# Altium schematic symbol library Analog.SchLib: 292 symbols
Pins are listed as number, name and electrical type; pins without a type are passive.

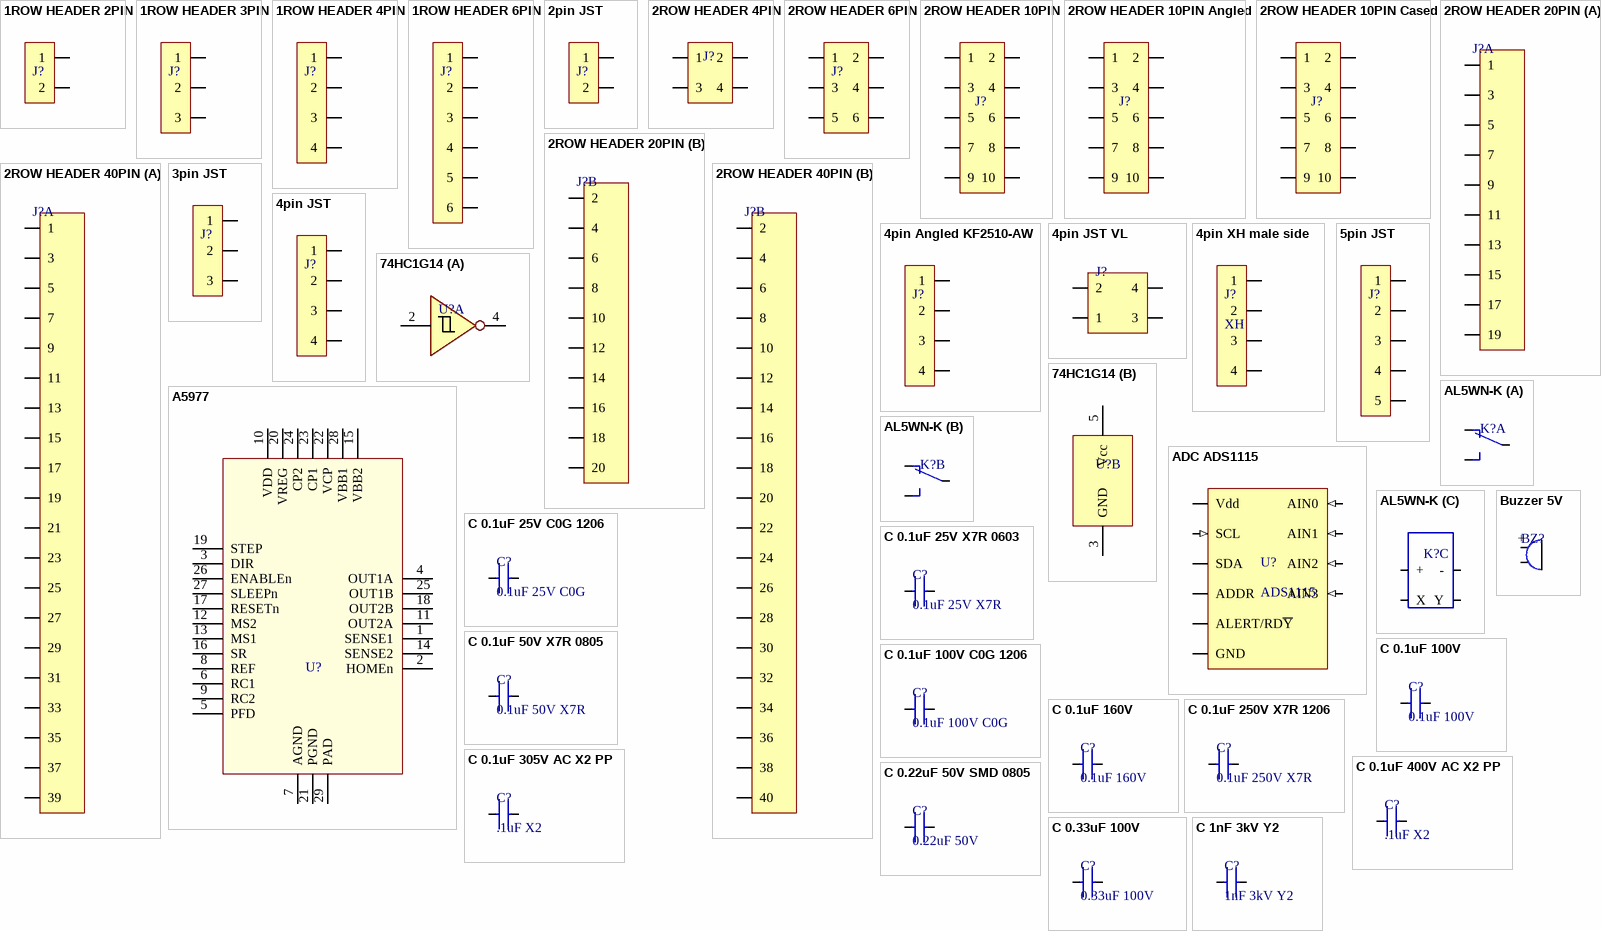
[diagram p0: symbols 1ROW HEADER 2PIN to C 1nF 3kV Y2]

## 1ROW HEADER 2PIN
designator J?  (value not drawn)
footprint 1ROW HEADER 2PIN (PEC02SAAN)
pins: 1, 2

## 1ROW HEADER 3PIN
designator J?  (value not drawn)
footprint 1ROW HEADER 3PIN (PEC03SAAN)
pins: 1, 2, 3

## 1ROW HEADER 4PIN
designator J?  (value not drawn)
footprint 1ROW HEADER 4PIN (PEC04SAAN)
pins: 1, 2, 3, 4

## 1ROW HEADER 6PIN
designator J?  (value not drawn)
footprint 1ROW HEADER 6PIN (PEC06SAAN)
pins: 1, 2, 3, 4, 5, 6

## 2pin JST
designator J?  (value not drawn)
footprint 2pin JST XH 2.5mm (B2B-XH)
pins: 1, 2

## 2ROW HEADER 4PIN
designator J?  (value not drawn)
footprint 2ROW HEADER 4PIN (PEC02SAAN)
pins: 1, 2, 3, 4

## 2ROW HEADER 6PIN
designator J?  (value not drawn)
footprint 2ROW HEADER 6PIN
pins: 1, 2, 3, 4, 5, 6

## 2ROW HEADER 10PIN
designator J?  (value not drawn)
footprint 2ROW HEADER 10PIN (PEC02SAAN)
pins: 1, 2, 3, 4, 5, 6, 7, 8, 9, 10

## 2ROW HEADER 10PIN Angled
designator J?  (value not drawn)
footprint 2ROW HEADER 10PIN Angled (2X05P)
pins: 1, 2, 3, 4, 5, 6, 7, 8, 9, 10

## 2ROW HEADER 10PIN Cased
designator J?  (value not drawn)
footprint 2ROW HEADER 10PIN CASED (PEC02SAAN)
pins: 1, 2, 3, 4, 5, 6, 7, 8, 9, 10

## 2ROW HEADER 20PIN
designator J?  (value not drawn)
footprint 2ROW HEADER 20PIN
part A pins: 1, 3, 5, 7, 9, 11, 13, 15, 17, 19
part B pins: 2, 4, 6, 8, 10, 12, 14, 16, 18, 20

## 2ROW HEADER 40PIN
designator J?  (value not drawn)
footprint 2ROW HEADER 40PIN
part A pins: 1, 3, 5, 7, 9, 11, 13, 15, 17, 19, 21, 23, 25, 27, 29, 31, 33, 35, 37, 39
part B pins: 2, 4, 6, 8, 10, 12, 14, 16, 18, 20, 22, 24, 26, 28, 30, 32, 34, 36, 38, 40

## 3pin JST
designator J?  (value not drawn)
footprint 3pin JST XH 2.5mm (B3B-XH)
pins: 1, 2, 3

## 4pin Angled KF2510-AW
designator J?  (value not drawn)
footprint 4pin KF2510-AW (KF2510-AW)
pins: 1, 2, 3, 4

## 4pin JST
designator J?  (value not drawn)
footprint 4pin JST XH 2.5mm (B4B-XH)
pins: 1, 2, 3, 4

## 4pin JST VL
designator J?  (value not drawn)
footprint 4pin JST VL (B04P-VL)
pins: 1, 2, 3, 4

## 4pin XH male side
designator J?, comment XH
footprint 4pin XH male side (S4B-XH-A-1)
pins: 1, 2, 3, 4

## 5pin JST
designator J?  (value not drawn)
footprint 5pin JST XH 2.5mm (B4B-XH)
pins: 1, 2, 3, 4, 5

## 74HC1G14
designator U?  (value not drawn)
footprint SOT-23-5-TI
part A pins: 2 In, 4 Out
part B pins: 3 GND, 5 Vcc

## A5977
designator U?  (value not drawn)
footprint TSSOP-28-EP
pins: 1 SENSE1, 2 HOMEn, 3 DIR, 4 OUT1A, 5 PFD, 6 RC1, 7 AGND, 8 REF, 9 RC2, 10 VDD, 11 OUT2A, 12 MS2, 13 MS1, 14 SENSE2, 15 VBB2, 16 SR, 17 RESETn, 18 OUT2B, 19 STEP, 20 VREG, 21 PGND, 22 VCP, 23 CP1, 24 CP2, 25 OUT1B, 26 ENABLEn, 27 SLEEPn, 28 VBB1, 29 PAD

## ADC ADS1115
designator U?, comment ADS1115
footprint MSOP-10-MCP; pin to pad ADDR>1 AIN0>4 AIN1>5 AIN2>6 AIN3>7 ALERT/RDY\>2 GND>3 SCL>10 SDA>9 Vdd>8
pins: ADDR, AIN0 (in), AIN1 (in), AIN2 (in), AIN3 (in), ALERT/RDY\, GND, SCL (in), SDA (io), Vdd (power)

## AL5WN-K
designator K?  (value not drawn)
Takamisawa Relay AL5WN-K
footprint Relay DIP10; pin to pad +>1 ->10 KA>3 KB>8 NCA>2 NCB>9 NOA>4 NOB>7 X>5 Y>6
footprint Relay DIP10; pin to pad +>1 ->10 KA>3 KB>8 NCA>2 NCB>9 NOA>4 NOB>7 X>5 Y>6
part A pins: KA, NCA, NOA
part B pins: KB, NCB, NOB
part C pins: +, -, X, Y

## Buzzer 5V
designator BZ?, comment BUZZER, 12mm X 9.5mm  (value not drawn)
footprint Buzzer (PEC02SAAN)
pins: +, -

## C 0.1uF 25V C0G 1206
designator C?, comment 0.1uF 25V C0G
footprint C np SMD 1206
pins: 1, 2

## C 0.1uF 25V X7R 0603
designator C?, comment 0.1uF 25V X7R
footprint C np SMD 0603
pins: 1, 2

## C 0.1uF 50V X7R 0805
designator C?, comment 0.1uF 50V X7R
footprint C np SMD 0805
pins: 1, 2

## C 0.1uF 100V
designator C?, comment 0.1uF 100V
footprint C np rect L5 D5 W7.2
pins: 1, 2

## C 0.1uF 100V C0G 1206
designator C?, comment 0.1uF 100V C0G
footprint C np SMD 1206
pins: 1, 2

## C 0.1uF 160V
designator C?, comment 0.1uF 160V
footprint C np rect L5 D9 W7.2
pins: 1, 2

## C 0.1uF 250V X7R 1206
designator C?, comment 0.1uF 250V X7R
footprint C np SMD 1206
pins: 1, 2

## C 0.1uF 305V AC X2 PP
designator C?, comment .1uF X2
footprint C np rect L15 D5.5 W18 (PP 0.1uF 630V)
pins: 1, 2

## C 0.1uF 400V AC X2 PP
designator C?, comment .1uF X2
footprint C np rect L15 D9 W18 (MKP1J031004J)
pins: 1, 2

## C 0.22uF 50V SMD 0805
designator C?, comment 0.22uF 50V
footprint C np SMD 0805
pins: 1, 2

## C 0.33uF 100V
designator C?, comment 0.33uF 100V
footprint C np rect L15 D8 W18 (PP 0.33uF 100V)
pins: 1, 2

## C 1nF 3kV Y2
designator C?, comment 1nF 3kV Y2
footprint C np Ceramic L7.5
pins: 1, 2

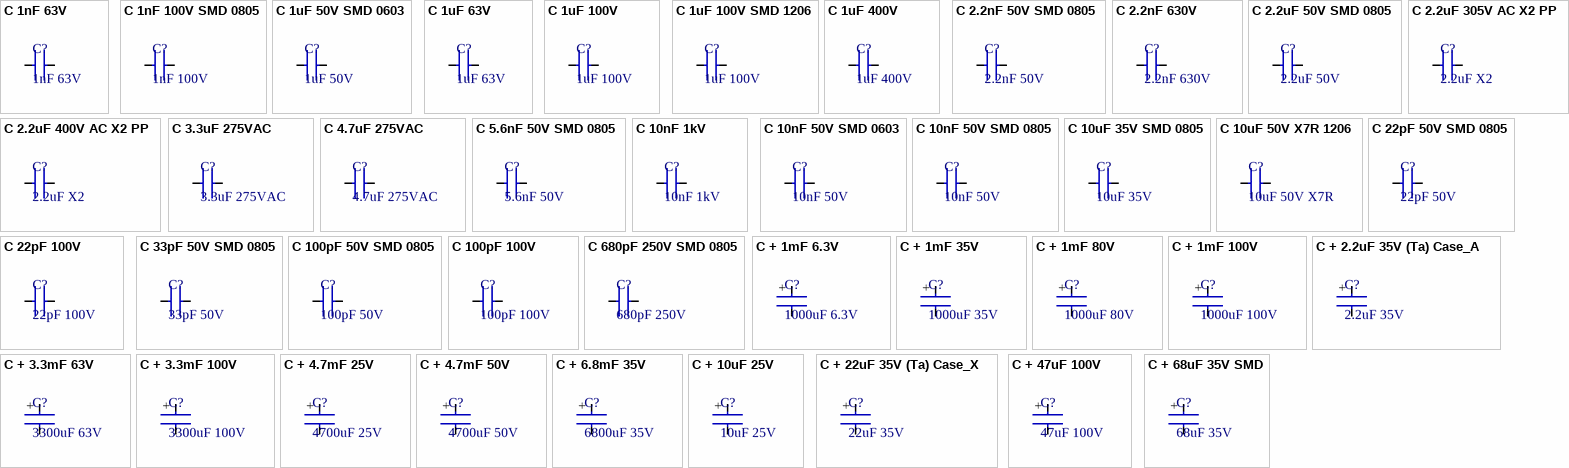
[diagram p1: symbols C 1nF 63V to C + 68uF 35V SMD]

## C 1nF 63V
designator C?, comment 1nF 63V
footprint C np rect L5 D2.5 W7.2
pins: 1, 2

## C 1nF 100V SMD 0805
designator C?, comment 1nF 100V
footprint C np SMD 0805
pins: 1, 2

## C 1uF 50V SMD 0603
designator C?, comment 1uF 50V
footprint C np SMD 0603
pins: 1, 2

## C 1uF 63V
designator C?, comment 1uF 63V
footprint C np rect L5 D6 W7.2
pins: 1, 2

## C 1uF 100V
designator C?, comment 1uF 100V
footprint C np rect L5 D7.2 W7.2
pins: 1, 2

## C 1uF 100V SMD 1206
designator C?, comment 1uF 100V
footprint C np SMD 1206
pins: 1, 2

## C 1uF 400V
designator C?, comment 1uF 400V
footprint C np rect L27.5 D11 W31 (MKP4-1/400/5P27)
pins: 1, 2

## C 2.2nF 50V SMD 0805
designator C?, comment 2.2nF 50V
footprint C np SMD 0805
pins: 1, 2

## C 2.2nF 630V
designator C?, comment 2.2nF 630V
footprint C np rect L5 D3 W7.2
pins: 1, 2

## C 2.2uF 50V SMD 0805
designator C?, comment 2.2uF 50V
footprint C np SMD 0805
pins: 1, 2

## C 2.2uF 305V AC X2 PP
designator C?, comment 2.2uF X2
footprint C np rect L27.5 D14 W31.5 (B32924C3225M189)
pins: 1, 2

## C 2.2uF 400V AC X2 PP
designator C?, comment 2.2uF X2
footprint C np rect L37.5 D20 W41.5 (MKP1J042207G)
pins: 1, 2

## C 3.3uF 275VAC
designator C?, comment 3.3uF 275VAC
footprint C np rect L27.5 D22 W31.5 (MP2335KGF8RLC)
pins: 1, 2

## C 4.7uF 275VAC
designator C?, comment 4.7uF 275VAC
footprint C np rect L27.5 D22 W31.5 (MP2335KGF8RLC)
pins: 1, 2

## C 5.6nF 50V SMD 0805
designator C?, comment 5.6nF 50V
footprint C np SMD 0805
pins: 1, 2

## C 10nF 1kV
designator C?, comment 10nF 1kV
footprint C np Ceramic L5
pins: 1, 2

## C 10nF 50V SMD 0603
designator C?, comment 10nF 50V
footprint C np SMD 0603
pins: 1, 2

## C 10nF 50V SMD 0805
designator C?, comment 10nF 50V
footprint C np SMD 0805
pins: 1, 2

## C 10uF 35V SMD 0805
designator C?, comment 10uF 35V
footprint C np SMD 0805
pins: 1, 2

## C 10uF 50V X7R 1206
designator C?, comment 10uF 50V X7R
footprint C np SMD 1206
pins: 1, 2

## C 22pF 50V SMD 0805
designator C?, comment 22pF 50V
footprint C np SMD 0805
pins: 1, 2

## C 22pF 100V
designator C?, comment 22pF 100V
footprint C np rect L5 D4.5 W7.2
pins: 1, 2

## C 33pF 50V SMD 0805
designator C?, comment 33pF 50V
footprint C np SMD 0805
pins: 1, 2

## C 100pF 50V SMD 0805
designator C?, comment 100pF 50V
footprint C np SMD 0805
pins: 1, 2

## C 100pF 100V
designator C?, comment 100pF 100V
footprint C np rect L5 D4.5 W7.2
pins: 1, 2

## C 680pF 250V SMD 0805
designator C?, comment 680pF 250V
footprint C np SMD 0805
pins: 1, 2

## C + 1mF 6.3V
designator C?, comment 1000uF 6.3V
footprint C + round L3.5 D8
pins: +, -

## C + 1mF 35V
designator C?, comment 1000uF 35V
footprint C + round L7.5 D16
pins: +, -

## C + 1mF 80V
designator C?, comment 1000uF 80V
footprint C + round L7.5 D18
pins: +, -

## C + 1mF 100V
designator C?, comment 1000uF 100V
footprint C + round L10 D20
pins: +, -

## C + 2.2uF 35V (Ta) Case_A
designator C?, comment 2.2uF 35V
footprint C + SMD Case-A 3216
pins: +, -

## C + 3.3mF 63V
designator C?, comment 3300uF 63V
footprint C + round L10 D20
pins: +, -

## C + 3.3mF 100V
designator C?, comment 3300uF 100V
footprint C + snap L10 D30
pins: +, -

## C + 4.7mF 25V
designator C?, comment 4700uF 25V
footprint C + round L7.5 D18
pins: +, -

## C + 4.7mF 50V
designator C?, comment 4700uF 50V
footprint C + round L10 D20
pins: +, -

## C + 6.8mF 35V
designator C?, comment 6800uF 35V
footprint C + round L7.5 D18
pins: +, -

## C + 10uF 25V
designator C?, comment 10uF 25V
footprint C + round L2.5 D6.5
pins: +, -

## C + 22uF 35V (Ta) Case_X
designator C?, comment 22uF 35V
footprint C + SMD Case-X 7343H
footprint C + SMD Case-X short
pins: +, -

## C + 47uF 100V
designator C?, comment 47uF 100V
footprint C + round L5 D10
pins: +, -

## C + 68uF 35V SMD
designator C?, comment 68uF 35V
footprint C + SMD rect 6.6
pins: +, -

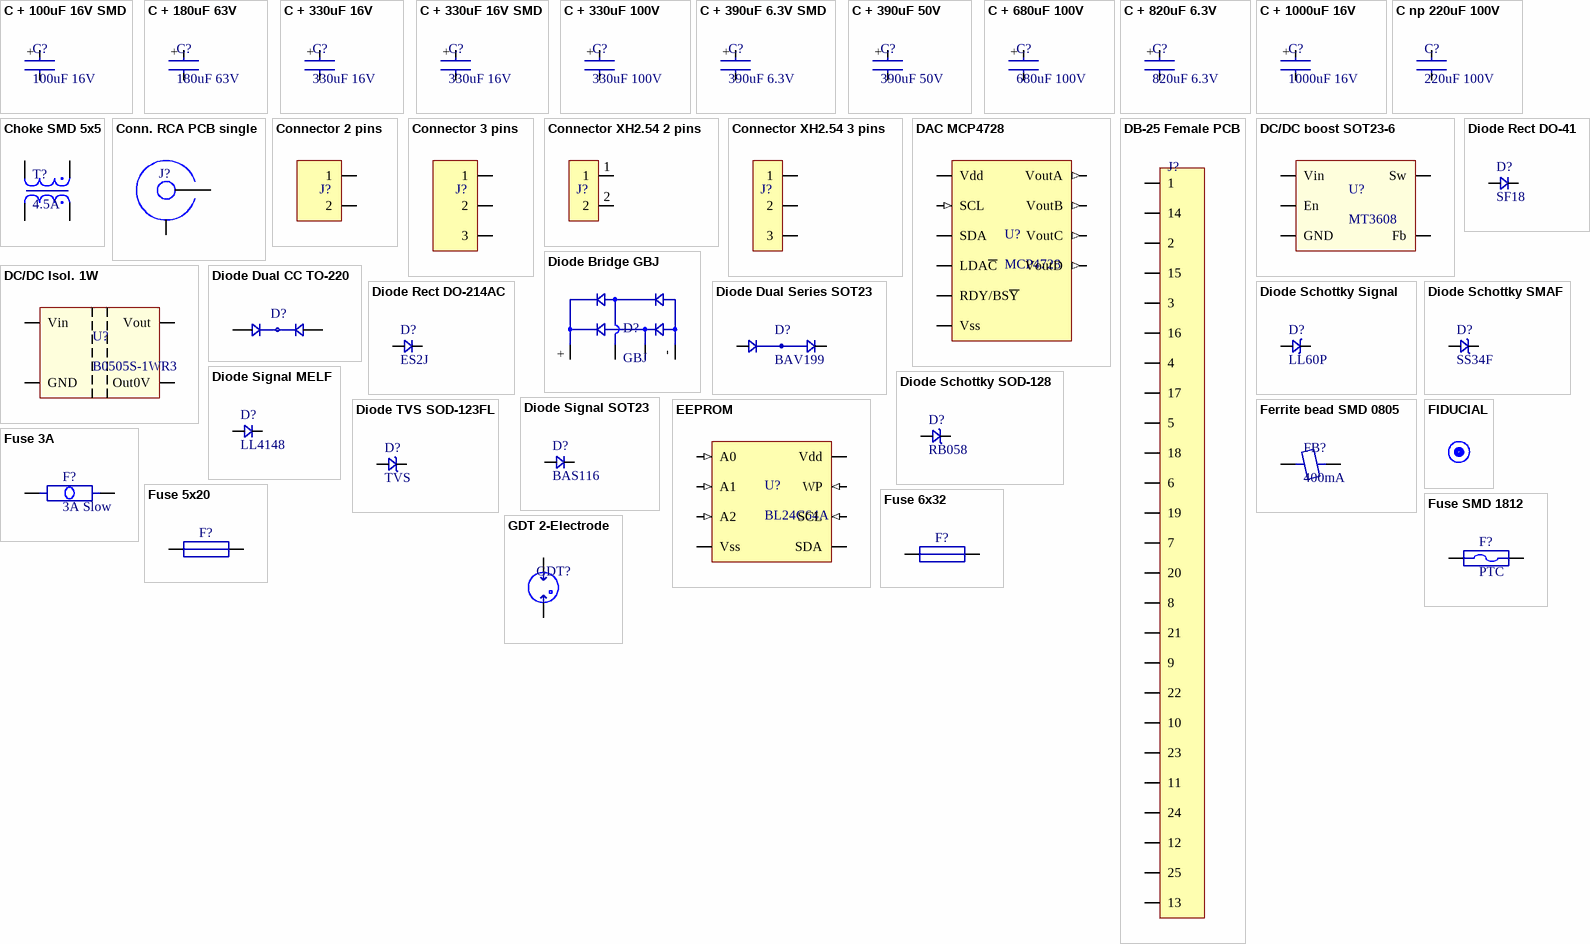
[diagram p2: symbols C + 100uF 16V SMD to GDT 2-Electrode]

## C + 100uF 16V SMD
designator C?, comment 100uF 16V
footprint C + SMD rect 6.6
pins: +, -

## C + 180uF 63V
designator C?, comment 180uF 63V
footprint C + round L5 D10
pins: +, -

## C + 330uF 16V
designator C?, comment 330uF 16V
footprint C + round L5 D10
pins: +, -

## C + 330uF 16V SMD
designator C?, comment 330uF 16V
footprint C + SMD rect 6.6
pins: +, -

## C + 330uF 100V
designator C?, comment 330uF 100V
footprint C + round L7.5 D16
pins: +, -

## C + 390uF 6.3V SMD
designator C?, comment 390uF 6.3V
footprint C + SMD rect 6.6
pins: +, -

## C + 390uF 50V
designator C?, comment 390uF 50V
footprint C + round L5 D12.5
pins: +, -

## C + 680uF 100V
designator C?, comment 680uF 100V
footprint C + round L7.5 D18
pins: +, -

## C + 820uF 6.3V
designator C?, comment 820uF 6.3V
footprint C + round L5 D10
pins: +, -

## C + 1000uF 16V
designator C?, comment 1000uF 16V
footprint C + round L5 D10
pins: +, -

## C np 220uF 100V
designator C?, comment 220uF 100V
footprint C NP round L7.5 D18
pins: 1, 2

## Choke SMD 5x5
designator T?, comment 4.5A
footprint Choke SMD 5x5
pins: 1, 2, 3, 4

## Conn. RCA PCB single
designator J?  (value not drawn)
footprint Conn. RCA PCB single
pins: 1, 2

## Connector 2 pins
designator J?  (value not drawn)
footprint Terminal 2pins
pins: 1, 2

## Connector 3 pins
designator J?  (value not drawn)
footprint Terminal 3pins
pins: 1, 2, 3

## Connector XH2.54 2 pins
designator J?  (value not drawn)
footprint Connector XH2.54 2 pins
footprint Connector XH2.54 2 pins
pins: 1, 2

## Connector XH2.54 3 pins
designator J?  (value not drawn)
footprint Connector XH2.54 3 pins
pins: 1, 2, 3

## DAC MCP4728
designator U?, comment MCP4728
footprint MSOP-10-MCP; pin to pad LDAC\>4 RDY/BSY\>5 SCL>2 SDA>3 Vdd>1 VoutA>6 VoutB>7 VoutC>8 VoutD>9 Vss>10
pins: LDAC\, RDY/BSY\, SCL (in), SDA (io), Vdd (power), VoutA (out), VoutB (out), VoutC (out), VoutD (out), Vss

## DB-25 Female PCB
designator J?  (value not drawn)
footprint DB-25 Female
pins: 1, 2, 3, 4, 5, 6, 7, 8, 9, 10, 11, 12, 13, 14, 15, 16, 17, 18, 19, 20, 21, 22, 23, 24, 25

## DC/DC boost SOT23-6
designator U?, comment MT3608
footprint SOT-23-6; pin to pad En>4 Fb>3 GND>2 Sw>1 Vin>5
pins: En, Fb, GND, Sw, Vin

## DC/DC Isol. 1W
designator U?, comment B0505S-1WR3
footprint DC-DC 4pin 1W (B0505S-1W); pin to pad GND>1 Out0V>3 Vin>2 Vout>4
pins: GND, Out0V, Vin, Vout

## Diode Bridge GBJ
designator D?, comment GBJ
footprint GBJ
pins: +, -, AC1, AC2

## Diode Dual CC TO-220
designator D?, comment MBRF1045  (value not drawn)
footprint TO-220-3-vertical; pin to pad A1>1 A2>3 K>2
pins: A1, A2, K

## Diode Dual Series SOT23
designator D?, comment BAV199
footprint SOT23 - Double Diode; pin to pad A>1 AK>3 K>2
pins: A, AK, K

## Diode Rect DO-41
designator D?, comment SF18
footprint DO-41
pins: A, K

## Diode Rect DO-214AC
designator D?, comment ES2J
footprint DO-214AC
pins: A, K

## Diode Schottky Signal
designator D?, comment LL60P
footprint LL34-D
pins: A, K

## Diode Schottky SMAF
designator D?, comment SS34F
footprint SMAF - DIODE
pins: A, K

## Diode Schottky SOD-128
designator D?, comment RB058
footprint SOD-128 - DIODE
pins: A, K

## Diode Signal MELF
designator D?, comment LL4148
footprint LL34-D
pins: A, K

## Diode Signal SOT23
designator D?, comment BAS116
footprint SOT23 - DIODE; pin to pad A>1 K>3
pins: A, K

## Diode TVS SOD-123FL
designator D?, comment TVS
footprint SOD-123FL - DIODE
pins: A, K

## EEPROM
designator U?, comment BL24C64A
footprint SO-8-TI; pin to pad A0>1 A1>2 A2>3 SCL>6 SDA>5 Vdd>8 Vss>4 WP>7
pins: A0 (in), A1 (in), A2 (in), SCL (in), SDA (io), Vdd (power), Vss, WP (in)

## Ferrite bead SMD 0805
designator FB?, comment 400mA
400mA, 0.2ohm, 220ohm @100MHz
footprint R SMD 0805
pins: 1, 2

## FIDUCIAL
designator F?  (value not drawn)
footprint FIDUCIAL
pins: 0

## Fuse 3A
designator F?, comment 3A Slow
footprint Fuse SMD 1206
pins: 1, 2

## Fuse 5x20
designator F?, comment Fuse  (value not drawn)
footprint Fuse 20x5 Holder
pins: 1, 2

## Fuse 6x32
designator F?, comment Fuse  (value not drawn)
footprint Fuse 6x32 Holder
pins: 1, 2

## Fuse SMD 1812
designator F?, comment PTC
footprint R SMD 1812
pins: 1, 2

## GDT 2-Electrode
designator GDT?  (value not drawn)
footprint GDT 2-Electrode
pins: 1, 2

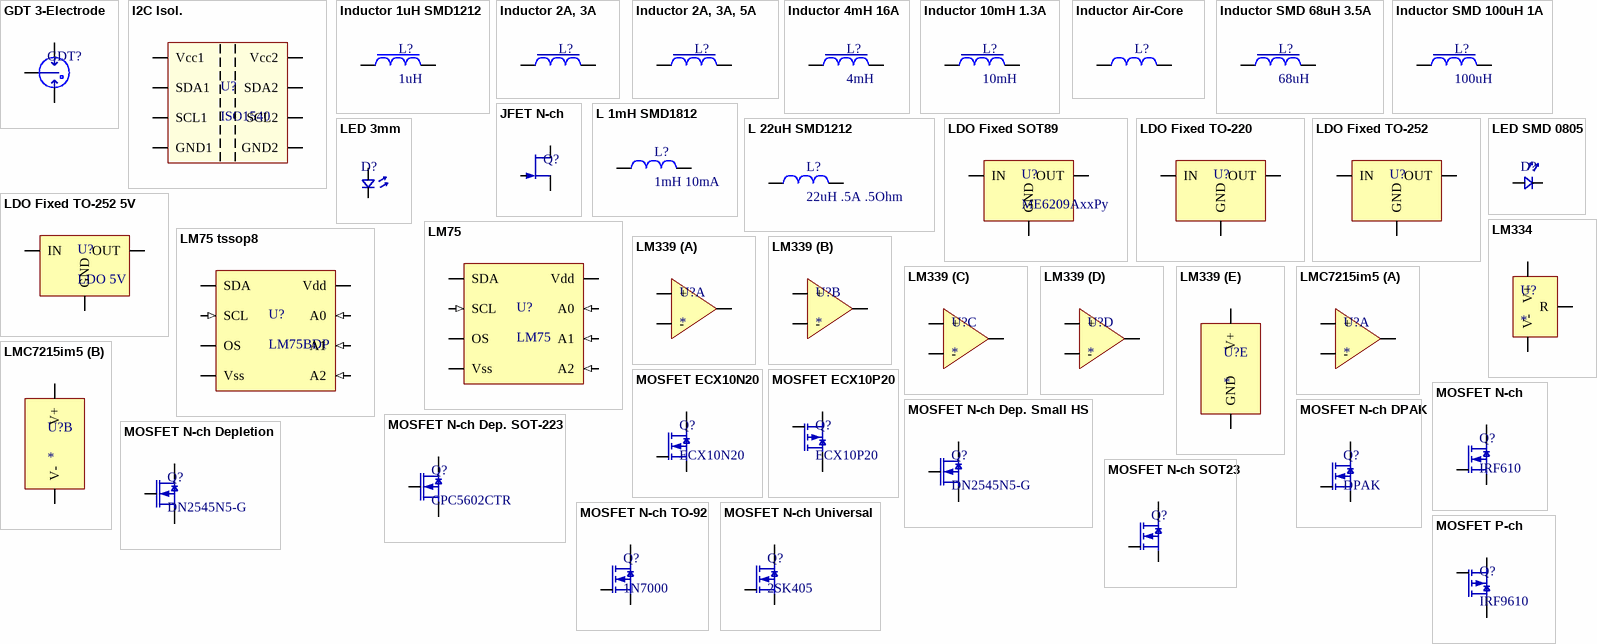
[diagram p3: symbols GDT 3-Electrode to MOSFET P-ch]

## GDT 3-Electrode
designator GDT?  (value not drawn)
footprint GDT 3-Electrode
pins: 1, 2, 3

## I2C Isol.
designator U?, comment ISO1540
footprint SO-8-TI; pin to pad GND1>4 GND2>5 SCL1>3 SCL2>6 SDA1>2 SDA2>7 Vcc1>1 Vcc2>8
pins: GND1, GND2, SCL1, SCL2, SDA1, SDA2, Vcc1, Vcc2

## Inductor 1uH SMD1212
designator L?, comment 1uH
footprint Inductor SMD 1212
pins: 1, 2

## Inductor 2A, 3A
designator L?  (value not drawn)
footprint Inductor 2A, 3A
pins: 1, 2

## Inductor 2A, 3A, 5A
designator L?  (value not drawn)
footprint Inductor 2A, 3A, 5A
pins: 1, 2

## Inductor 4mH 16A
designator L?, comment 4mH
footprint Inductor 16A
pins: 1, 2

## Inductor 10mH 1.3A
designator L?, comment 10mH
footprint Inductor 10mH 1A
pins: 1, 2

## Inductor Air-Core
designator L?  (value not drawn)
footprint Inductor Air-Core L12.7
pins: 1, 2

## Inductor SMD 68uH 3.5A
designator L?, comment 68uH
footprint Inductor SMD 12.5x12.5mm
pins: 1, 2

## Inductor SMD 100uH 1A
designator L?, comment 100uH
footprint Inductor SMD 10.1x10.1
pins: 1, 2

## JFET N-ch
designator Q?  (value not drawn)
footprint TO-92; pin to pad D>1 G>3 S>2
pins: D, G, S

## L 1mH SMD1812
designator L?, comment 1mH 10mA
footprint Inductor SMD 1812
pins: 1, 2

## L 22uH SMD1212
designator L?, comment 22uH .5A .5Ohm
footprint Inductor SMD 1212
pins: 1, 2

## LDO Fixed SOT89
designator U?, comment ME6209AxxPy
footprint SOT-89; pin to pad GND>1 IN>2 OUT>3
pins: GND, IN, OUT

## LDO Fixed TO-220
designator U?  (value not drawn)
footprint TO-220-3-HeatSink; pin to pad GND>2 IN>1 OUT>3
pins: GND, IN, OUT

## LDO Fixed TO-252
designator U?  (value not drawn)
footprint TO-252-3; pin to pad GND>2 IN>1 OUT>3
pins: GND, IN, OUT

## LDO Fixed TO-252 5V
designator U?, comment LDO 5V
footprint TO-252-3; pin to pad GND>2 IN>1 OUT>3
pins: GND, IN, OUT

## LED 3mm
designator D?  (value not drawn)
footprint LED 3MM
pins: A, K

## LED SMD 0805
designator D?  (value not drawn)
footprint LED SMD 0805
footprint LED SMD 0805
pins: A, C

## LM75
designator U?
footprint SO-8-TI; pin to pad A0>7 A1>6 A2>5 OS>3 SCL>2 SDA>1 Vdd>8 Vss>4
pins: A0 (in), A1 (in), A2 (in), OS (oc), SCL (in), SDA (io), Vdd (power), Vss

## LM75 tssop8
designator U?, comment LM75BDP
footprint TSSOP8-NXP; pin to pad A0>7 A1>6 A2>5 OS>3 SCL>2 SDA>1 Vdd>8 Vss>4
pins: A0 (in), A1 (in), A2 (in), OS (oc), SCL (in), SDA (io), Vdd (power), Vss

## LM334
designator U?
footprint LM334
pins: R, V+, V-

## LM339
designator U?
footprint SOP-14-TI; pin to pad GND>12 IN+A>5 IN+B>7 IN+C>9 IN+D>11 IN-A>4 IN-B>6 IN-C>8 IN-D>10 OUTA>2 OUTB>1 OUTC>14 OUTD>13 V+>3
part A pins: IN+A +, IN-A -, OUTA OUT
part B pins: IN+B +, IN-B -, OUTB OUT
part C pins: IN+C +, IN-C -, OUTC OUT
part D pins: IN+D +, IN-D -, OUTD OUT
part E pins: GND, V+

## LMC7215im5
designator U?
footprint SOT-23-5-TI; pin to pad IN+A>3 IN-A>4 OUTA>1 V+>2 V->5
part A pins: IN+A +, IN-A -, OUTA OUT
part B pins: V+, V-

## MOSFET ECX10N20
designator Q?, comment ECX10N20
footprint TO-247-3-vertical; pin to pad D>3 G>1 S>2
pins: D, G, S

## MOSFET ECX10P20
designator Q?, comment ECX10P20
footprint TO-247-3-vertical; pin to pad D>3 G>1 S>2
pins: D, G, S

## MOSFET N-ch
designator Q?, comment IRF610
footprint TO-220-3-vertical; pin to pad D>2 G>1 S>3
pins: D, G, S

## MOSFET N-ch Dep. Small HS
designator Q?, comment DN2545N5-G
footprint TO-220-3-Small-HeatSink; pin to pad D>2 G>1 S>3
pins: D, G, S

## MOSFET N-ch Dep. SOT-223
designator Q?, comment CPC5602CTR
footprint SOT-223; pin to pad D>2 G>1 S>3
pins: D, G, S

## MOSFET N-ch Depletion
designator Q?, comment DN2545N5-G
footprint TO-220-3-vertical; pin to pad D>2 G>1 S>3
pins: D, G, S

## MOSFET N-ch DPAK
designator Q?, comment DPAK
footprint DPAK; pin to pad D>2 G>1 S>3
pins: D, G, S

## MOSFET N-ch SOT23
designator Q?, comment SOT23  (value not drawn)
footprint SOT23; pin to pad D>3 G>1 S>2
pins: D, G, S

## MOSFET N-ch TO-92
designator Q?, comment 1N7000
footprint TO-92; pin to pad D>3 G>2 S>1
pins: D, G, S

## MOSFET N-ch Universal
designator Q?, comment 2SK405
footprint TO-247-TO-220; pin to pad D>2 G>1 S>3
pins: D, G, S

## MOSFET P-ch
designator Q?, comment IRF9610
footprint TO-220-3-vertical; pin to pad D>2 G>1 S>3
pins: D, G, S

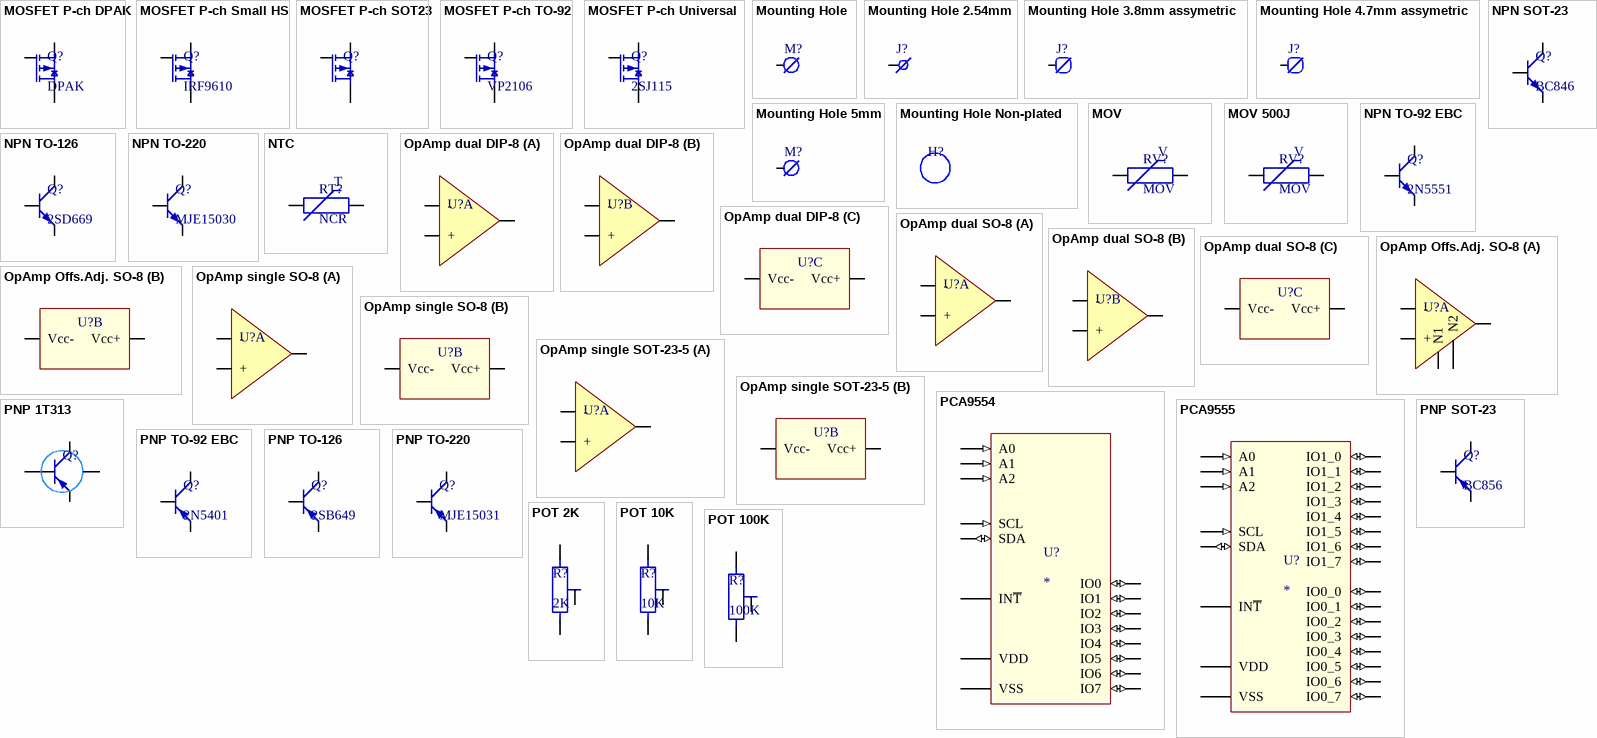
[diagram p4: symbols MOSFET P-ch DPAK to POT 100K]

## MOSFET P-ch DPAK
designator Q?, comment DPAK
footprint DPAK; pin to pad D>2 G>1 S>3
pins: D, G, S

## MOSFET P-ch Small HS
designator Q?, comment IRF9610
footprint TO-220-3-Small-HeatSink; pin to pad D>2 G>1 S>3
pins: D, G, S

## MOSFET P-ch SOT23
designator Q?, comment SOT23  (value not drawn)
footprint SOT23; pin to pad D>3 G>1 S>2
pins: D, G, S

## MOSFET P-ch TO-92
designator Q?, comment VP2106
footprint TO-92; pin to pad D>3 G>2 S>1
pins: D, G, S

## MOSFET P-ch Universal
designator Q?, comment 2SJ115
footprint TO-247-TO-220; pin to pad D>2 G>1 S>3
pins: D, G, S

## Mounting Hole
designator M?  (value not drawn)
footprint Mounting Hole
pins: 0

## Mounting Hole 2.54mm
designator J?  (value not drawn)
footprint Mounting Hole 2.54mm
pins: 0

## Mounting Hole 3.8mm assymetric
designator J?  (value not drawn)
footprint Mounting Hole 3.8mm assymetric
pins: 0

## Mounting Hole 4.7mm assymetric
designator J?  (value not drawn)
footprint Mounting Hole 4.7mm assymetric
pins: 0

## Mounting Hole 5mm
designator M?  (value not drawn)
footprint Mounting Hole 5mm
pins: 0

## Mounting Hole Non-plated
designator H?  (value not drawn)
footprint Mounting Hole Non-Plated

## MOV
designator RV?
footprint MOV
pins: 1, 2

## MOV 500J
designator RV?, comment MOV
footprint MOV 500J
pins: 1, 2

## NPN SOT-23
designator Q?, comment BC846
footprint SOT23 - npn; pin to pad B>1 C>3 E>2
pins: B, C, E

## NPN TO-92 EBC
designator Q?, comment 2N5551
footprint TO-92; pin to pad B>2 C>3 E>1
pins: B, C, E

## NPN TO-126
designator Q?, comment 2SD669
footprint TO-126F-3-vertical; pin to pad B>3 C>2 E>1
pins: B, C, E

## NPN TO-220
designator Q?, comment MJE15030
footprint TO-220-3-vertical; pin to pad B>1 C>2 E>3
pins: B, C, E

## NTC
designator RT?, comment NCR
footprint NTC
pins: 1, 2

## OpAmp dual DIP-8
designator U?, comment LM4562NA  (value not drawn)
footprint DIP8; pin to pad A_IN+>3 A_IN->2 A_OUT>1 B_IN+>5 B_IN->6 B_OUT>7 Vcc+>8 Vcc->4
part A pins: A_IN+ +, A_IN- -, A_OUT OUT
part B pins: B_IN+ +, B_IN- -, B_OUT OUT
part C pins: Vcc+, Vcc-

## OpAmp dual SO-8
designator U?, comment LM4562MA  (value not drawn)
footprint SO-8-TI; pin to pad A_IN+>3 A_IN->2 A_OUT>1 B_IN+>5 B_IN->6 B_OUT>7 Vcc+>8 Vcc->4
part A pins: A_IN+ +, A_IN- -, A_OUT OUT
part B pins: B_IN+ +, B_IN- -, B_OUT OUT
part C pins: Vcc+, Vcc-

## OpAmp Offs.Adj. SO-8
designator U?  (value not drawn)
footprint SO-8-TI; pin to pad IN+>3 IN->2 N1>1 N2>5 OUT>6 Vcc+>7 Vcc->4
part A pins: IN+ +, IN- -, N1, N2, OUT
part B pins: Vcc+, Vcc-

## OpAmp single SO-8
designator U?, comment TP07  (value not drawn)
footprint SO-8-TI; pin to pad IN+>3 IN->2 OUT>6 Vcc+>7 Vcc->4
part A pins: IN+ +, IN- -, OUT
part B pins: Vcc+, Vcc-

## OpAmp single SOT-23-5
designator U?, comment GS8591-TR  (value not drawn)
footprint SOT-23-5-TI; pin to pad IN+>3 IN->4 OUT>1 Vcc+>5 Vcc->2
part A pins: IN+ +, IN- -, OUT
part B pins: Vcc+, Vcc-

## PCA9554
designator U?
Value: PCA9554
footprint TSSOP16-NXP; pin to pad A0>1 A1>2 A2>3 INT\>13 IO0>4 IO1>5 IO2>6 IO3>7 IO4>9 IO5>10 IO6>11 IO7>12 SCL>14 SDA>15 VDD>16 VSS>8
pins: A0 (in), A1 (in), A2 (in), INT\ (oc), IO0 (io), IO1 (io), IO2 (io), IO3 (io), IO4 (io), IO5 (io), IO6 (io), IO7 (io), SCL (in), SDA (io), VDD (power), VSS (power)

## PCA9555
designator U?
Value: PCA9555
footprint TSSOP24-NXP; pin to pad A0>21 A1>2 A2>3 INT\>1 IO0_0>4 IO0_1>5 IO0_2>6 IO0_3>7 IO0_4>8 IO0_5>9 IO0_6>10 IO0_7>11 IO1_0>13 IO1_1>14 IO1_2>15 IO1_3>16 IO1_4>17 IO1_5>18 IO1_6>19 IO1_7>20 SCL>22 SDA>23 VDD>24 VSS>12
pins: A0 (in), A1 (in), A2 (in), INT\ (oc), IO0_0 (io), IO0_1 (io), IO0_2 (io), IO0_3 (io), IO0_4 (io), IO0_5 (io), IO0_6 (io), IO0_7 (io), IO1_0 (io), IO1_1 (io), IO1_2 (io), IO1_3 (io), IO1_4 (io), IO1_5 (io), IO1_6 (io), IO1_7 (io), SCL (in), SDA (io), VDD (power), VSS (power)

## PNP 1T313
designator Q?  (value not drawn)
footprint 1T313
pins: B, C, Case, E

## PNP SOT-23
designator Q?, comment BC856
footprint SOT23 - pnp; pin to pad B>1 C>3 E>2
pins: B, C, E

## PNP TO-92 EBC
designator Q?, comment 2N5401
footprint TO-92; pin to pad B>2 C>3 E>1
pins: B, C, E

## PNP TO-126
designator Q?, comment 2SB649
footprint TO-126F-3-vertical; pin to pad B>3 C>2 E>1
pins: B, C, E

## PNP TO-220
designator Q?, comment MJE15031
footprint TO-220-3-vertical; pin to pad B>1 C>2 E>3
pins: B, C, E

## POT 2K
designator R?, comment 2K
footprint POT
pins: L, R, TAP

## POT 10K
designator R?, comment 10K
footprint POT
pins: L, R, TAP

## POT 100K
designator R?, comment 100K
footprint POT
pins: L, R, TAP

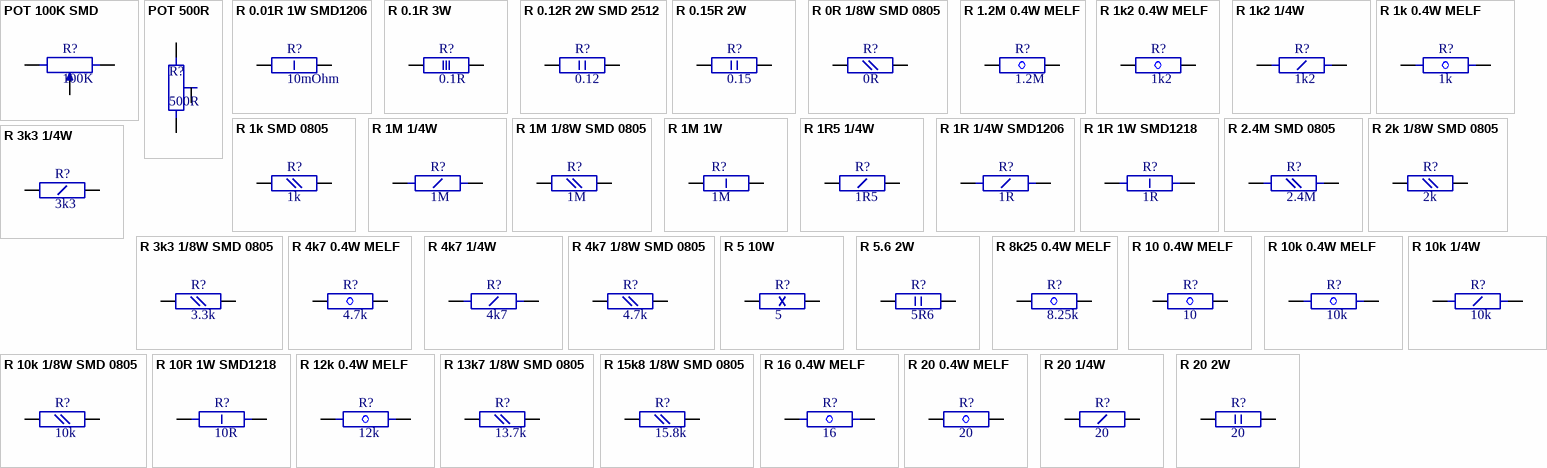
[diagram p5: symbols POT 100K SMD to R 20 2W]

## POT 100K SMD
designator R?, comment 100K
footprint POT SMD
pins: L, R, TAP

## POT 500R
designator R?, comment 500R
footprint POT
pins: L, R, TAP

## R 0.01R 1W SMD1206
designator R?, comment 10mOhm
footprint R SMD 1206
pins: 1, 2

## R 0.1R 3W
designator R?, comment 0.1R
footprint R L25 D6 W17.5
pins: 1, 2

## R 0.12R 2W SMD 2512
designator R?, comment 0.12
footprint R SMD 2512
pins: 1, 2

## R 0.15R 2W
designator R?, comment 0.15
footprint R L15 D4.6 W12 seat/stand
pins: 1, 2

## R 0R 1/8W SMD 0805
designator R?, comment 0R
footprint R SMD 0805
pins: 1, 2

## R 1.2M 0.4W MELF
designator R?, comment 1.2M
footprint R MMA 0204
pins: 1, 2

## R 1k2 0.4W MELF
designator R?, comment 1k2
footprint R MMA 0204
pins: 1, 2

## R 1k2 1/4W
designator R?, comment 1k2
footprint R L10 D2.5 W6.3
pins: 1, 2

## R 1k 0.4W MELF
designator R?, comment 1k
footprint R MMA 0204
pins: 1, 2

## R 1k SMD 0805
designator R?, comment 1k
footprint R SMD 0805
pins: 1, 2

## R 1M 1/4W
designator R?, comment 1M
footprint R L10 D2.5 W6.3
pins: 1, 2

## R 1M 1/8W SMD 0805
designator R?, comment 1M
footprint R SMD 0805
pins: 1, 2

## R 1M 1W
designator R?, comment 1M
footprint R L15 D4.6 W12
pins: 1, 2

## R 1R5 1/4W
designator R?, comment 1R5
footprint R L10 D2.5 W6.3
pins: 1, 2

## R 1R 1/4W SMD1206
designator R?, comment 1R
footprint R SMD 1206
pins: 1, 2

## R 1R 1W SMD1218
designator R?, comment 1R
footprint R SMD 1218
pins: 1, 2

## R 2.4M SMD 0805
designator R?, comment 2.4M
footprint R SMD 0805
pins: 1, 2

## R 2k 1/8W SMD 0805
designator R?, comment 2k
footprint R SMD 0805
pins: 1, 2

## R 3k3 1/4W
designator R?, comment 3k3
footprint R L10 D2.5 W6.3
pins: 1, 2

## R 3k3 1/8W SMD 0805
designator R?, comment 3.3k
footprint R SMD 0805
pins: 1, 2

## R 4k7 0.4W MELF
designator R?, comment 4.7k
footprint R MMA 0204
pins: 1, 2

## R 4k7 1/4W
designator R?, comment 4k7
footprint R L10 D2.5 W6.3
pins: 1, 2

## R 4k7 1/8W SMD 0805
designator R?, comment 4.7k
footprint R SMD 0805
pins: 1, 2

## R 5 10W
designator R?, comment 5
footprint R L46 D9 W36.5
pins: 1, 2

## R 5.6 2W
designator R?, comment 5R6
footprint R L15 D3.7 W11
pins: 1, 2

## R 8k25 0.4W MELF
designator R?, comment 8.25k
footprint R MMA 0204
pins: 1, 2

## R 10 0.4W MELF
designator R?, comment 10
footprint R MMA 0204
pins: 1, 2

## R 10k 0.4W MELF
designator R?, comment 10k
footprint R MMA 0204
pins: 1, 2

## R 10k 1/4W
designator R?, comment 10k
footprint R L10 D2.5 W6.3
pins: 1, 2

## R 10k 1/8W SMD 0805
designator R?, comment 10k
footprint R SMD 0805
pins: 1, 2

## R 10R 1W SMD1218
designator R?, comment 10R
footprint R SMD 1218
pins: 1, 2

## R 12k 0.4W MELF
designator R?, comment 12k
footprint R MMA 0204
pins: 1, 2

## R 13k7 1/8W SMD 0805
designator R?, comment 13.7k
footprint R SMD 0805
pins: 1, 2

## R 15k8 1/8W SMD 0805
designator R?, comment 15.8k
footprint R SMD 0805
pins: 1, 2

## R 16 0.4W MELF
designator R?, comment 16
footprint R MMA 0204
pins: 1, 2

## R 20 0.4W MELF
designator R?, comment 20
footprint R MMA 0204
pins: 1, 2

## R 20 1/4W
designator R?, comment 20
footprint R L10 D2.5 W6.3
pins: 1, 2

## R 20 2W
designator R?, comment 20
footprint R L15 D4.6 W12
pins: 1, 2

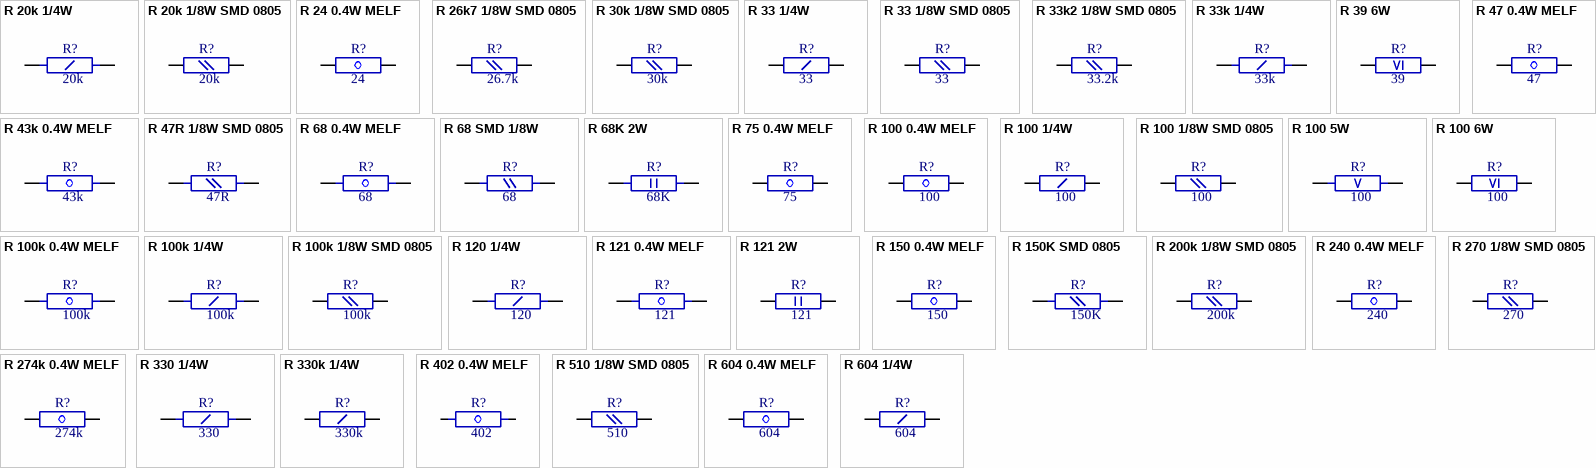
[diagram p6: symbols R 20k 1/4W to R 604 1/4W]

## R 20k 1/4W
designator R?, comment 20k
footprint R L10 D2.5 W6.3
pins: 1, 2

## R 20k 1/8W SMD 0805
designator R?, comment 20k
footprint R SMD 0805
pins: 1, 2

## R 24 0.4W MELF
designator R?, comment 24
footprint R MMA 0204
pins: 1, 2

## R 26k7 1/8W SMD 0805
designator R?, comment 26.7k
footprint R SMD 0805
pins: 1, 2

## R 30k 1/8W SMD 0805
designator R?, comment 30k
footprint R SMD 0805
pins: 1, 2

## R 33 1/4W
designator R?, comment 33
footprint R L10 D2.5 W6.3
pins: 1, 2

## R 33 1/8W SMD 0805
designator R?, comment 33
footprint R SMD 0805
pins: 1, 2

## R 33k2 1/8W SMD 0805
designator R?, comment 33.2k
footprint R SMD 0805
pins: 1, 2

## R 33k 1/4W
designator R?, comment 33k
footprint R L10 D2.5 W6.3
pins: 1, 2

## R 39 6W
designator R?, comment 39
footprint R L30.5 D8 W23.5
pins: 1, 2

## R 43k 0.4W MELF
designator R?, comment 43k
footprint R MMA 0204
pins: 1, 2

## R 47 0.4W MELF
designator R?, comment 47
footprint R MMA 0204
pins: 1, 2

## R 47R 1/8W SMD 0805
designator R?, comment 47R
footprint R SMD 0805
pins: 1, 2

## R 68 0.4W MELF
designator R?, comment 68
footprint R MMA 0204
pins: 1, 2

## R 68 SMD 1/8W
designator R?, comment 68
footprint R SMD 0805
pins: 1, 2

## R 68K 2W
designator R?, comment 68K
footprint R L15 D4.6 W12
pins: 1, 2

## R 75 0.4W MELF
designator R?, comment 75
footprint R MMA 0204
pins: 1, 2

## R 100 0.4W MELF
designator R?, comment 100
footprint R MMA 0204
pins: 1, 2

## R 100 1/4W
designator R?, comment 100
footprint R L10 D2.5 W6.3
pins: 1, 2

## R 100 1/8W SMD 0805
designator R?, comment 100
footprint R SMD 0805
pins: 1, 2

## R 100 5W
designator R?, comment 100
footprint R L27.5 D9.6 W22.2
pins: 1, 2

## R 100 6W
designator R?, comment 100
footprint R L30.5 D8 W23.5
pins: 1, 2

## R 100k 0.4W MELF
designator R?, comment 100k
footprint R MMA 0204
pins: 1, 2

## R 100k 1/4W
designator R?, comment 100k
footprint R L10 D2.5 W6.3
pins: 1, 2

## R 100k 1/8W SMD 0805
designator R?, comment 100k
footprint R SMD 0805
pins: 1, 2

## R 120 1/4W
designator R?, comment 120
footprint R L10 D2.5 W6.3
pins: 1, 2

## R 121 0.4W MELF
designator R?, comment 121
footprint R MMA 0204
pins: 1, 2

## R 121 2W
designator R?, comment 121
footprint R L15 D3.7 W11
pins: 1, 2

## R 150 0.4W MELF
designator R?, comment 150
footprint R MMA 0204
pins: 1, 2

## R 150K SMD 0805
designator R?, comment 150K
footprint R SMD 0805
pins: 1, 2

## R 200k 1/8W SMD 0805
designator R?, comment 200k
footprint R SMD 0805
pins: 1, 2

## R 240 0.4W MELF
designator R?, comment 240
footprint R MMA 0204
pins: 1, 2

## R 270 1/8W SMD 0805
designator R?, comment 270
footprint R SMD 0805
pins: 1, 2

## R 274k 0.4W MELF
designator R?, comment 274k
footprint R MMA 0204
pins: 1, 2

## R 330 1/4W
designator R?, comment 330
footprint R L10 D2.5 W6.3
pins: 1, 2

## R 330k 1/4W
designator R?, comment 330k
footprint R L10 D2.5 W6.3
pins: 1, 2

## R 402 0.4W MELF
designator R?, comment 402
footprint R MMA 0204
pins: 1, 2

## R 510 1/8W SMD 0805
designator R?, comment 510
footprint R SMD 0805
pins: 1, 2

## R 604 0.4W MELF
designator R?, comment 604
footprint R MMA 0204
pins: 1, 2

## R 604 1/4W
designator R?, comment 604
footprint R L10 D2.5 W6.3
pins: 1, 2

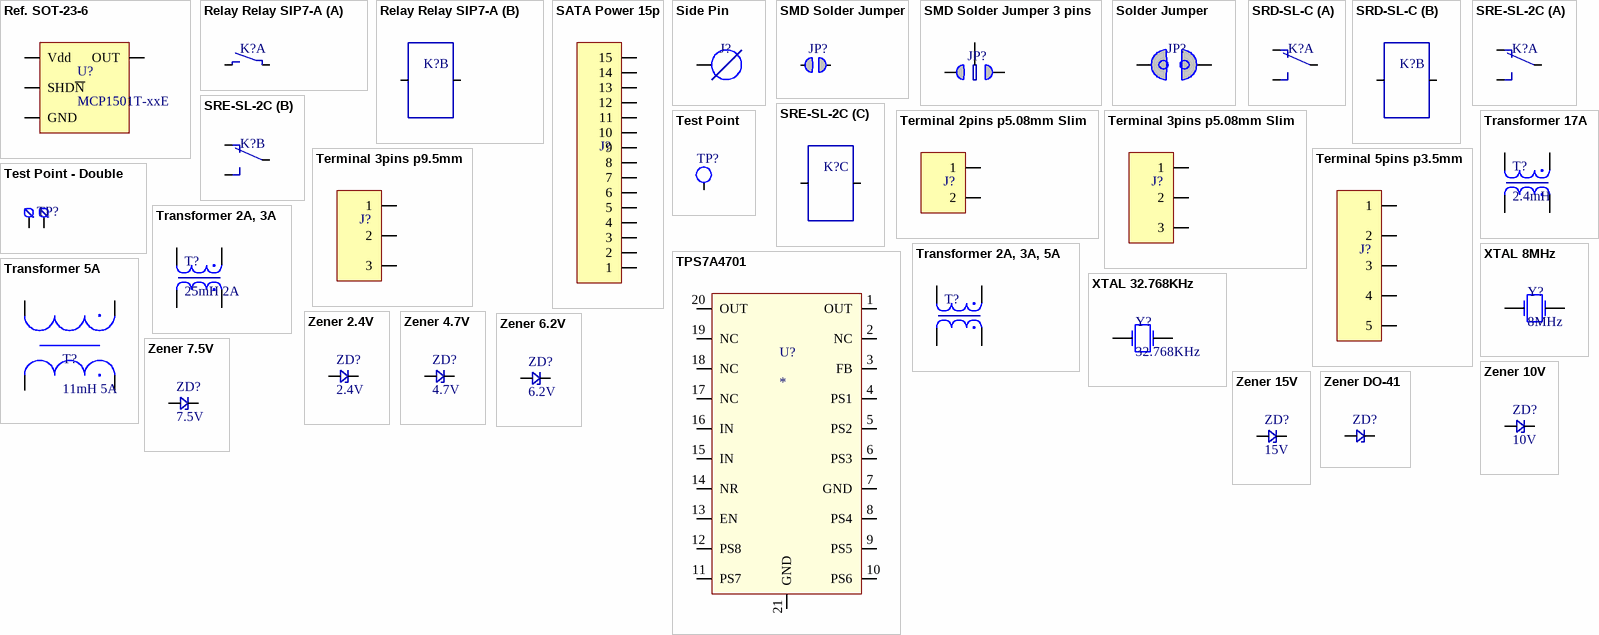
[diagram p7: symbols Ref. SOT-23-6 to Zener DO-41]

## Ref. SOT-23-6
designator U?, comment MCP1501T-xxE
footprint SOT-23-6; pin to pad GND>2+3+5 OUT>1 SHDN\>4 Vdd>6
pins: GND, OUT, SHDN\, Vdd

## Relay Relay SIP7-A
designator K?  (value not drawn)
Relay Relay SIP7-A; Value: SIP-1A05
footprint Relay Reed SIP7-A; pin to pad +>3 ->5 K>7 NO>1
part A pins: K, NO
part B pins: +, -

## SATA Power 15p
designator J?  (value not drawn)
footprint SATA Power 15p
pins: 1, 2, 3, 4, 5, 6, 7, 8, 9, 10, 11, 12, 13, 14, 15

## Side Pin
designator J?  (value not drawn)
footprint Side Pin
footprint Side Pin
pins: 0

## SMD Solder Jumper
designator JP?  (value not drawn)
footprint SMD SOLDER JUMPER
pins: 1, 2

## SMD Solder Jumper 3 pins
designator JP?  (value not drawn)
footprint SMD SOLDER JUMPER 3 PINS
footprint SMD SOLDER JUMPER 3 PINS
pins: 1, 2, 3

## Solder Jumper
designator JP?  (value not drawn)
footprint Solder Jumper
pins: 1, 2

## SRD-SL-C
designator K?  (value not drawn)
Songle Relay SRD-05VDC-SL-C
footprint SRD-SL-C (Songle Relay 5pin)
part A pins: K, NC, NO
part B pins: X, Y

## SRE-SL-2C
designator K?  (value not drawn)
Songle Relay SRE-05VDC-SL-2C
footprint SRE-SL-2C (Songle Relay 8pin)
part A pins: KA, NCA, NOA
part B pins: KB, NCB, NOB
part C pins: X, Y

## Terminal 2pins p5.08mm Slim
designator J?  (value not drawn)
footprint Terminal 2pins Slim
pins: 1, 2

## Terminal 3pins p5.08mm Slim
designator J?  (value not drawn)
footprint Terminal 3pins Slim
pins: 1, 2, 3

## Terminal 3pins p9.5mm
designator J?  (value not drawn)
footprint Terminal 3pins p9.5mm
pins: 1, 2, 3

## Terminal 5pins p3.5mm
designator J?  (value not drawn)
footprint Terminal 5pins P3.5mm (XK128L-3.5MM)
pins: 1, 2, 3, 4, 5

## Test Point
designator TP?  (value not drawn)
footprint Test Point
pins: 0

## Test Point - Double
designator TP?  (value not drawn)
footprint 1ROW HEADER 2PIN (PEC02SAAN)
pins: 1, 2

## TPS7A4701
designator U?
footprint QFN-20
footprint QFN-20
pins: 1 OUT, 2 NC, 3 FB, 4 PS1, 5 PS2, 6 PS3, 7 GND, 8 PS4, 9 PS5, 10 PS6, 11 PS7, 12 PS8, 13 EN, 14 NR, 15 IN, 16 IN, 17 NC, 18 NC, 19 NC, 20 OUT, 21 GND

## Transformer 2A, 3A
designator T?, comment 25mH 2A
footprint Transformer 2A, 3A
pins: 1, 2, 3, 4

## Transformer 2A, 3A, 5A
designator T?, comment 25mH 2A  (value not drawn)
footprint Transformer 2A, 3A, 5A
pins: 1, 2, 3, 4

## Transformer 5A
designator T?, comment 11mH 5A
footprint Transformer 5A
pins: 1, 2, 3, 4

## Transformer 17A
designator T?, comment 2.4mH
footprint Transformer 17A
pins: 1, 2, 3, 4

## XTAL 8MHz
designator Y?, comment 8MHz
footprint XTAL 5032
pins: 1, 2

## XTAL 32.768KHz
designator Y?, comment 32.768KHz
footprint XTAL 3215
pins: 1, 2

## Zener 2.4V
designator ZD?, comment 2.4V
footprint LL34
pins: A, K

## Zener 4.7V
designator ZD?, comment 4.7V
footprint LL34
pins: A, K

## Zener 6.2V
designator ZD?, comment 6.2V
footprint LL34
pins: A, K

## Zener 7.5V
designator ZD?, comment 7.5V
footprint LL34
pins: A, K

## Zener 10V
designator ZD?, comment 10V
footprint LL34
pins: A, K

## Zener 15V
designator ZD?, comment 15V
footprint LL34-W
pins: A, K

## Zener DO-41
designator ZD?, comment 15V  (value not drawn)
footprint DO-41 Zener
pins: A, K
